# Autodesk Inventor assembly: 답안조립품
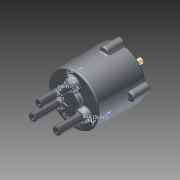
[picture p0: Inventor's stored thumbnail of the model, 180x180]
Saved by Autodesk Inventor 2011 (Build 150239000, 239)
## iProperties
Created: 2015-05
Part Number: 답안조립품
Document SubType Name: Assembly
Designer: Administrator
Mass: 2160.23 g
Surface Area: 1801.24 cm^2
Volume: 438.519 cm^3
Density: 4.92619 g/cm^3
Author: Administrator
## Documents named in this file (14)
- C:\Users\Administrator\Desktop\Inventor1급\Inventor1급-김진원\답안조립품.iam
- C:\Users\Administrator\Desktop\Inventor1급\Inventor1급-김진원\몸체.ipt
- C:\Users\Administrator\Desktop\Inventor1급\Inventor1급-김진원\판캠.ipt
- C:\Users\Administrator\Desktop\Inventor1급\Inventor1급-김진원\메인 축.ipt
- C:\Users\Administrator\Desktop\Inventor1급\Inventor1급-김진원\멈춤링 22 x 1.2.ipt
- C:\Users\Administrator\Desktop\Inventor1급\Inventor1급-김진원\베어링 NA 4900.ipt
- C:\Users\Administrator\Desktop\Inventor1급\Inventor1급-김진원\멈춤링 10 x 1.ipt
- C:\Users\Administrator\Desktop\Inventor1급\Inventor1급-김진원\슬라이드 축.ipt
- C:\Users\Administrator\Desktop\Inventor1급\Inventor1급-김진원\커버.ipt
- C:\Users\Administrator\Desktop\Inventor1급\Inventor1급-김진원\오일실.ipt
- C:\Users\Administrator\Desktop\Inventor1급\Inventor1급-김진원\M5x0.5x20.ipt
- C:\Users\Administrator\Desktop\Inventor1급\Inventor1급-김진원\가변 스프링-01.ipt
- C:\Users\Administrator\Desktop\Inventor1급\Inventor1급-김진원\가변 스프링-02.ipt
- C:\Users\Administrator\Desktop\Inventor1급\Inventor1급-김진원\가변 스프링-03.ipt
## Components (7 placed, 4 different names)
1. 가변 스프링-01:1
2. 가변 스프링-02:1
3. 가변 스프링-03:1
4. M5x0.5x20:1
5. M5x0.5x20:2
6. M5x0.5x20:3
7. M5x0.5x20:4
